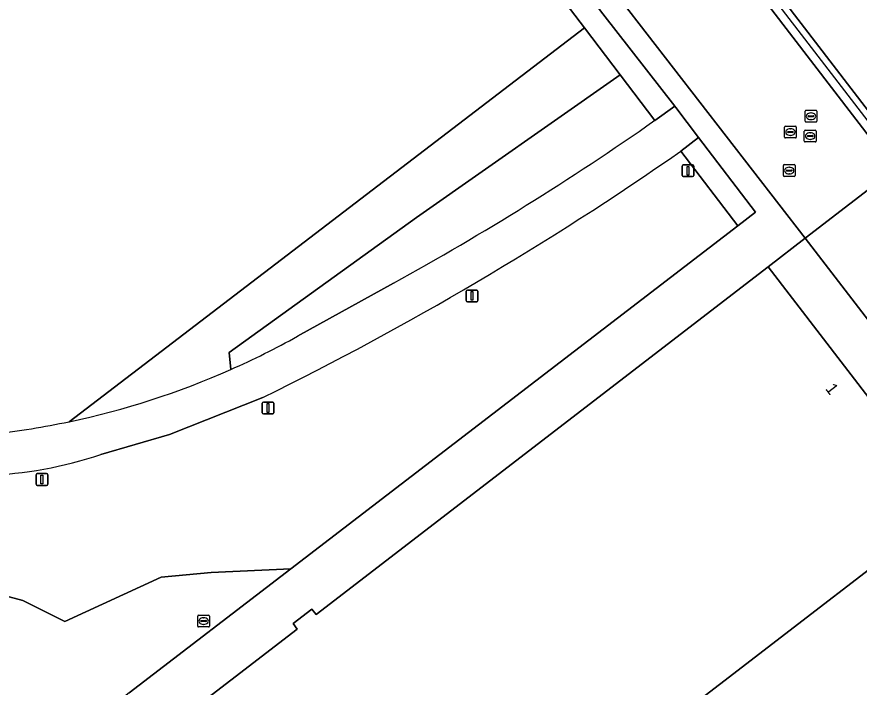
# Model space of a CAD drawing. Extents: x 155209 to 156748, y 385356 to 388487.
# Drawn here: x 156106.4 to 156177.8, y 385937.7 to 385994.6 of the extents above; entities that cross this region are included whole.
import ezdxf

# ---------------------------------------------------------------- set-up
doc = ezdxf.new("R2010")
doc.units = 0
for name, color, linetype in [('IMGEO_Grasland_agrarisch', 7, 'Continuous'), ('IMGEO_Groenvoorziening', 7, 'Continuous'), ('IMGEO_Haag', 7, 'Continuous'), ('IMGEO_Lichtmast', 7, 'Continuous'), ('IMGEO_Loofbos', 7, 'Continuous'), ('IMGEO_Pand', 7, 'Continuous'), ('IMGEO_Pand_nummerreeks', 7, 'Continuous'), ('IMGEO_Rijbaan_lokaal_gesloten', 7, 'Continuous'), ('IMGEO_Rijbaan_lokaal_open', 7, 'Continuous'), ('IMGEO_Rioolput', 7, 'Continuous'), ('IMGEO_Voetpad_gesloten', 7, 'Continuous'), ('IMGEO_Voetpad_open', 7, 'Continuous')]:
    doc.layers.add(name, color=color, linetype=linetype)

msp = doc.modelspace()

# ---------------------------------------------------------------- linework, layer by layer
at = {"layer": 'IMGEO_Grasland_agrarisch'}
msp.add_lwpolyline([(156220.549, 385968.739), (156185.49, 386016.084), (156167.209, 386001.475), (156278.587, 385856.453)], dxfattribs=at)
at = {"layer": 'IMGEO_Groenvoorziening'}
for points in [[(156285.514, 385849.881), (156284.854, 385850.065), (156278.587, 385856.453), (156167.209, 386001.475), (156185.49, 386016.084), (156184.674, 386017.186), (156177.537, 386011.492), (156166.201, 386002.568), (156165.304, 386001.86), (156168.669, 385997.526), (156180.839, 385981.624), (156184.09, 385977.376), (156195.93, 385961.982), (156207.756, 385946.593), (156219.573, 385931.238), (156231.41, 385915.868), (156241.752, 385902.4), (156255.401, 385884.633), (156266.626, 385870.03), (156277.503, 385855.777), (156277.531, 385855.74)], [(156157.568, 385989.652), (156154.535, 385993.632), (156110.792, 385960.218)], [(156124.515, 385964.645), (156124.385, 385966.102), (156140.278, 385977.551), (156157.568, 385989.652)], [(156160.509, 385985.793), (156157.568, 385989.652), (156140.278, 385977.551), (156124.385, 385966.102), (156124.515, 385964.645)], [(156167.554, 385976.836), (156162.729, 385983.183)], [(156088.771, 385944.146), (156096.563, 385945.599), (156102.938, 385946.083), (156106.886, 385945.056), (156110.425, 385943.255), (156118.61, 385947.023), (156122.858, 385947.408), (156129.607, 385947.725), (156167.554, 385976.836)], [(156130.189, 385967.476), (156138.317, 385971.979)], [(156127.24, 385962.271), (156119.321, 385959.145), (156113.496, 385957.432)], [(156129.607, 385947.725), (156122.858, 385947.408), (156118.61, 385947.023), (156110.425, 385943.255), (156106.886, 385945.056), (156102.938, 385946.083), (156096.563, 385945.599), (156088.771, 385944.146)], [(156115.909, 385937.216), (156129.607, 385947.725)]]:
    msp.add_lwpolyline(points, dxfattribs=at)
for centre, radius, start, end in [((156023.199, 386181.648), 239.193, 298.76895, 305.03364), ((156006.38, 386207.947), 273.795, 296.19475, 304.82294), ((156096.586, 386027.723), 68.985, 293.88235, 299.15078), ((156096.616, 386027.646), 68.902, 281.87329, 293.88581), ((156102.561, 385990.002), 34.357, 271.89192, 288.55928)]:
    msp.add_arc(centre, radius, start, end, dxfattribs=at)
at = {"layer": 'IMGEO_Haag'}
msp.add_lwpolyline([(156167.209, 386001.475), (156166.781, 386001.086), (156222.38, 385928.805), (156278.346, 385855.875), (156284.439, 385849.436), (156284.854, 385850.065), (156278.587, 385856.453)], close=True, dxfattribs=at)
at = {"layer": 'IMGEO_Lichtmast'}
for p, q in [((156162.821, 385981.114), (156162.821, 385981.914)), ((156162.821, 385981.914), (156162.821, 385981.114)), ((156162.921, 385982.014), (156163.711, 385982.014)), ((156163.711, 385982.014), (156162.921, 385982.014)), ((156163.811, 385981.914), (156163.811, 385981.114)), ((156163.811, 385981.114), (156163.811, 385981.914)), ((156163.711, 385981.014), (156162.921, 385981.014)), ((156162.921, 385981.014), (156163.711, 385981.014)), ((156144.507, 385970.494), (156144.507, 385971.294)), ((156144.507, 385971.294), (156144.507, 385970.494)), ((156144.607, 385971.394), (156145.397, 385971.394)), ((156145.397, 385971.394), (156144.607, 385971.394)), ((156145.497, 385971.294), (156145.497, 385970.494)), ((156145.497, 385970.494), (156145.497, 385971.294)), ((156145.397, 385970.394), (156144.607, 385970.394)), ((156144.607, 385970.394), (156145.397, 385970.394)), ((156127.193, 385960.984), (156127.193, 385961.784)), ((156127.193, 385961.784), (156127.193, 385960.984)), ((156127.293, 385961.884), (156128.083, 385961.884)), ((156128.083, 385961.884), (156127.293, 385961.884)), ((156128.183, 385961.784), (156128.183, 385960.984)), ((156128.183, 385960.984), (156128.183, 385961.784)), ((156128.083, 385960.884), (156127.293, 385960.884)), ((156127.293, 385960.884), (156128.083, 385960.884)), ((156107.995, 385954.916), (156107.995, 385955.716)), ((156107.995, 385955.716), (156107.995, 385954.916)), ((156108.095, 385955.816), (156108.885, 385955.816)), ((156108.885, 385955.816), (156108.095, 385955.816)), ((156108.985, 385955.716), (156108.985, 385954.916)), ((156108.985, 385954.916), (156108.985, 385955.716)), ((156108.885, 385954.816), (156108.095, 385954.816)), ((156108.095, 385954.816), (156108.885, 385954.816))]:
    msp.add_line(p, q, dxfattribs=at)
for points in [[(156163.241, 385981.889), (156163.391, 385981.889), (156163.391, 385981.139), (156163.241, 385981.139), (156163.241, 385981.889)], [(156144.927, 385971.269), (156145.077, 385971.269), (156145.077, 385970.519), (156144.927, 385970.519), (156144.927, 385971.269)], [(156127.613, 385961.759), (156127.763, 385961.759), (156127.763, 385961.009), (156127.613, 385961.009), (156127.613, 385961.759)], [(156108.415, 385955.691), (156108.565, 385955.691), (156108.565, 385954.941), (156108.415, 385954.941), (156108.415, 385955.691)]]:
    msp.add_lwpolyline(points, dxfattribs=at)
for centre, start, end in [((156162.921, 385981.914), 90, 180), ((156162.921, 385981.914), 90, 180), ((156163.711, 385981.914), 0, 90), ((156163.711, 385981.914), 360, 90), ((156162.921, 385981.114), 180, 270), ((156162.921, 385981.114), 180, 270), ((156163.711, 385981.114), 270, 0), ((156163.711, 385981.114), 270, 0), ((156144.607, 385971.294), 90, 180), ((156144.607, 385971.294), 90, 180), ((156145.397, 385971.294), 0, 90), ((156145.397, 385971.294), 360, 90), ((156144.607, 385970.494), 180, 270), ((156144.607, 385970.494), 180, 270), ((156145.397, 385970.494), 270, 0), ((156145.397, 385970.494), 270, 0), ((156127.293, 385961.784), 90, 180), ((156127.293, 385961.784), 90, 180), ((156128.083, 385961.784), 0, 90), ((156128.083, 385961.784), 360, 90), ((156127.293, 385960.984), 180, 270), ((156127.293, 385960.984), 180, 270), ((156128.083, 385960.984), 270, 0), ((156128.083, 385960.984), 270, 0), ((156108.095, 385955.716), 90, 180), ((156108.095, 385955.716), 90, 180), ((156108.885, 385955.716), 0, 90), ((156108.885, 385955.716), 360, 90), ((156108.095, 385954.916), 180, 270), ((156108.095, 385954.916), 180, 270), ((156108.885, 385954.916), 270, 0), ((156108.885, 385954.916), 270, 0)]:
    msp.add_arc(centre, 0.1, start, end, dxfattribs=at)
at = {"layer": 'IMGEO_Loofbos'}
msp.add_lwpolyline([(156110.792, 385960.218), (156154.535, 385993.632), (156144.769, 386006.447), (156173.258, 386028.793)], dxfattribs=at)
msp.add_arc((156096.443, 386028.664), 69.934, 276.51645, 281.83971, dxfattribs=at)
at = {"layer": 'IMGEO_Pand'}
msp.add_lwpolyline([(156146.274, 385922.751), (156185.717, 385953.089), (156170.127, 385973.357), (156131.765, 385943.857), (156131.406, 385944.305), (156129.815, 385943.105), (156130.161, 385942.624), (156050.588, 385881.441)], dxfattribs=at)
at = {"layer": 'IMGEO_Rijbaan_lokaal_gesloten'}
for points in [[(156277.531, 385855.74), (156277.503, 385855.777), (156266.626, 385870.03), (156255.401, 385884.633), (156241.752, 385902.4), (156231.41, 385915.868), (156219.573, 385931.238), (156207.756, 385946.593), (156195.93, 385961.982), (156184.09, 385977.376), (156180.839, 385981.624), (156173.28, 385975.806), (156273.756, 385845.152), (156253.997, 385829.921), (156263.096, 385818.018), (156247.187, 385805.769), (156251.992, 385799.487), (156244.172, 385793.446), (156247.412, 385789.224), (156247.701, 385788.833), (156251.441, 385783.91), (156235.908, 385771.977), (156239.22, 385767.734), (156228.894, 385759.732)], [(156273.756, 385845.152), (156173.28, 385975.806), (156170.127, 385973.357), (156185.717, 385953.089), (156146.274, 385922.751), (156150.528, 385917.222), (156156.102, 385921.509), (156164.09, 385911.123), (156158.516, 385906.837), (156160.857, 385903.793), (156200.3, 385934.128), (156216.362, 385913.247), (156216.482, 385913.09), (156177.035, 385882.729), (156191.619, 385863.794), (156231.059, 385894.15)]]:
    msp.add_lwpolyline(points, dxfattribs=at)
at = {"layer": 'IMGEO_Rijbaan_lokaal_open'}
msp.add_lwpolyline([(156165.304, 386001.86), (156166.201, 386002.568), (156177.537, 386011.492), (156184.674, 386017.186), (156187.011, 386019.05), (156185.798, 386019.909), (156176.524, 386026.479), (156150.284, 386005.616), (156156.897, 385996.959), (156157.631, 385995.998), (156173.28, 385975.806), (156180.839, 385981.624), (156168.669, 385997.526)], close=True, dxfattribs=at)
at = {"layer": 'IMGEO_Rioolput'}
for p, q in [((156173.261, 385985.717), (156173.261, 385986.569)), ((156173.336, 385986.643), (156174.188, 385986.643)), ((156173.52, 385986.137), (156173.52, 385986.149)), ((156173.958, 385986.1), (156173.56, 385986.1)), ((156173.563, 385986.186), (156173.961, 385986.186)), ((156173.749, 385986.423), (156173.774, 385986.423)), ((156174.004, 385986.149), (156174.004, 385986.137)), ((156174.262, 385986.569), (156174.262, 385985.717)), ((156171.59, 385985.296), (156172.442, 385985.296)), ((156174.188, 385985.643), (156173.336, 385985.643)), ((156173.772, 385985.863), (156173.747, 385985.863)), ((156171.515, 385984.37), (156171.515, 385985.222)), ((156171.774, 385984.79), (156171.774, 385984.802)), ((156172.212, 385984.753), (156171.814, 385984.753)), ((156171.817, 385984.839), (156172.215, 385984.839)), ((156172.003, 385985.076), (156172.028, 385985.076)), ((156172.258, 385984.802), (156172.258, 385984.79)), ((156172.516, 385985.222), (156172.516, 385984.37)), ((156173.196, 385984.031), (156173.196, 385984.883)), ((156173.271, 385984.957), (156174.123, 385984.957)), ((156173.684, 385984.737), (156173.709, 385984.737)), ((156174.197, 385984.883), (156174.197, 385984.031)), ((156172.442, 385984.296), (156171.59, 385984.296)), ((156172.026, 385984.516), (156172.001, 385984.516)), ((156174.123, 385983.957), (156173.271, 385983.957)), ((156173.455, 385984.451), (156173.455, 385984.463)), ((156173.893, 385984.414), (156173.495, 385984.414)), ((156173.498, 385984.5), (156173.896, 385984.5)), ((156173.707, 385984.177), (156173.682, 385984.177)), ((156173.939, 385984.463), (156173.939, 385984.451)), ((156171.416, 385981.107), (156171.416, 385981.959)), ((156171.491, 385982.033), (156172.343, 385982.033)), ((156171.904, 385981.813), (156171.929, 385981.813)), ((156172.417, 385981.959), (156172.417, 385981.107)), ((156172.343, 385981.033), (156171.491, 385981.033)), ((156171.675, 385981.527), (156171.675, 385981.539)), ((156172.113, 385981.49), (156171.715, 385981.49)), ((156171.718, 385981.576), (156172.116, 385981.576)), ((156171.927, 385981.253), (156171.902, 385981.253)), ((156172.159, 385981.539), (156172.159, 385981.527)), ((156121.716, 385942.873), (156121.716, 385943.725)), ((156121.791, 385943.799), (156122.643, 385943.799)), ((156121.975, 385943.293), (156121.975, 385943.305)), ((156122.413, 385943.256), (156122.015, 385943.256)), ((156122.018, 385943.342), (156122.416, 385943.342)), ((156122.204, 385943.579), (156122.229, 385943.579)), ((156122.459, 385943.305), (156122.459, 385943.293)), ((156122.717, 385943.725), (156122.717, 385942.873)), ((156122.643, 385942.799), (156121.791, 385942.799)), ((156122.227, 385943.019), (156122.202, 385943.019))]:
    msp.add_line(p, q, dxfattribs=at)
for points in [[(156173.261, 385985.717), (156173.261, 385986.569)], [(156173.336, 385986.643), (156174.188, 385986.643)], [(156174.262, 385986.569), (156174.262, 385985.717)], [(156171.59, 385985.296), (156172.442, 385985.296)], [(156174.188, 385985.643), (156173.336, 385985.643)], [(156171.515, 385984.37), (156171.515, 385985.222)], [(156172.516, 385985.222), (156172.516, 385984.37)], [(156173.196, 385984.031), (156173.196, 385984.883)], [(156173.271, 385984.957), (156174.123, 385984.957)], [(156174.197, 385984.883), (156174.197, 385984.031)], [(156172.442, 385984.296), (156171.59, 385984.296)], [(156174.123, 385983.957), (156173.271, 385983.957)], [(156171.416, 385981.107), (156171.416, 385981.959)], [(156171.491, 385982.033), (156172.343, 385982.033)], [(156172.417, 385981.959), (156172.417, 385981.107)], [(156172.343, 385981.033), (156171.491, 385981.033)], [(156121.716, 385942.873), (156121.716, 385943.725)], [(156121.791, 385943.799), (156122.643, 385943.799)], [(156122.717, 385943.725), (156122.717, 385942.873)], [(156122.643, 385942.799), (156121.791, 385942.799)]]:
    msp.add_lwpolyline(points, dxfattribs=at)
for centre, radius, start, end in [((156173.338, 385986.567), 0.0765, 91.55205, 178.44795), ((156173.338, 385986.567), 0.0765, 91.55205, 178.44795), ((156173.56, 385986.146), 0.0403, 85.87752, 175.75265), ((156173.557, 385986.136), 0.0366, 178.93798, 274.71019), ((156173.961, 385986.143), 0.043, 264.86636, 352.45326), ((156173.965, 385986.148), 0.0386, 1.73085, 96.63898), ((156174.186, 385986.567), 0.0765, 1.55205, 88.44795), ((156174.186, 385986.567), 0.0765, 1.55205, 88.44795), ((156171.592, 385985.22), 0.0765, 91.55205, 178.44795), ((156171.592, 385985.22), 0.0765, 91.55205, 178.44795), ((156172.44, 385985.22), 0.0765, 1.55205, 88.44795), ((156172.44, 385985.22), 0.0765, 1.55205, 88.44795), ((156173.338, 385985.719), 0.0765, 181.55205, 268.44795), ((156173.338, 385985.719), 0.0765, 181.55205, 268.44795), ((156174.186, 385985.719), 0.0765, 271.55205, 358.44795), ((156174.186, 385985.719), 0.0765, 271.55205, 358.44795), ((156171.814, 385984.799), 0.0403, 85.87752, 175.75265), ((156171.811, 385984.789), 0.0366, 178.93798, 274.71019), ((156172.215, 385984.796), 0.043, 264.86636, 352.45326), ((156172.219, 385984.801), 0.0386, 1.73085, 96.63898), ((156173.273, 385984.881), 0.0765, 91.55205, 178.44795), ((156173.273, 385984.881), 0.0765, 91.55205, 178.44795), ((156174.121, 385984.881), 0.0765, 1.55205, 88.44795), ((156174.121, 385984.881), 0.0765, 1.55205, 88.44795), ((156171.592, 385984.372), 0.0765, 181.55205, 268.44795), ((156171.592, 385984.372), 0.0765, 181.55205, 268.44795), ((156172.44, 385984.372), 0.0765, 271.55205, 358.44795), ((156172.44, 385984.372), 0.0765, 271.55205, 358.44795), ((156173.273, 385984.033), 0.0765, 181.55205, 268.44795), ((156173.273, 385984.033), 0.0765, 181.55205, 268.44795), ((156173.495, 385984.46), 0.0403, 85.87752, 175.75265), ((156173.492, 385984.45), 0.0366, 178.93798, 274.71019), ((156173.896, 385984.457), 0.043, 264.86636, 352.45326), ((156173.9, 385984.462), 0.0386, 1.73085, 96.63898), ((156174.121, 385984.033), 0.0765, 271.55205, 358.44795), ((156174.121, 385984.033), 0.0765, 271.55205, 358.44795), ((156171.493, 385981.957), 0.0765, 91.55205, 178.44795), ((156171.493, 385981.957), 0.0765, 91.55205, 178.44795), ((156172.341, 385981.957), 0.0765, 1.55205, 88.44795), ((156172.341, 385981.957), 0.0765, 1.55205, 88.44795), ((156171.493, 385981.109), 0.0765, 181.55205, 268.44795), ((156171.493, 385981.109), 0.0765, 181.55205, 268.44795), ((156171.715, 385981.536), 0.0403, 85.87752, 175.75265), ((156171.712, 385981.526), 0.0366, 178.93798, 274.71019), ((156172.116, 385981.533), 0.043, 264.86636, 352.45326), ((156172.12, 385981.538), 0.0386, 1.73085, 96.63898), ((156172.341, 385981.109), 0.0765, 271.55205, 358.44795), ((156172.341, 385981.109), 0.0765, 271.55205, 358.44795), ((156121.793, 385943.723), 0.0765, 91.55205, 178.44795), ((156121.793, 385943.723), 0.0765, 91.55205, 178.44795), ((156122.015, 385943.302), 0.0403, 85.87752, 175.75265), ((156122.012, 385943.292), 0.0366, 178.93798, 274.71019), ((156122.416, 385943.299), 0.043, 264.86636, 352.45326), ((156122.42, 385943.304), 0.0386, 1.73085, 96.63898), ((156122.641, 385943.723), 0.0765, 1.55205, 88.44795), ((156122.641, 385943.723), 0.0765, 1.55205, 88.44795), ((156121.793, 385942.875), 0.0765, 181.55205, 268.44795), ((156121.793, 385942.875), 0.0765, 181.55205, 268.44795), ((156122.641, 385942.875), 0.0765, 271.55205, 358.44795), ((156122.641, 385942.875), 0.0765, 271.55205, 358.44795)]:
    msp.add_arc(centre, radius, start, end, dxfattribs=at)
for centre, major_axis, ratio, start_param, end_param in [((156173.748, 385986.143), (-0.387, 0.002), 0.722429, 4.712389, 7.853982), ((156173.773, 385986.143), (-0.39, 0.002), 0.717154, 1.570796, 4.712389), ((156172.002, 385984.796), (-0.387, 0.002), 0.722429, 4.712389, 7.853982), ((156172.027, 385984.796), (-0.39, 0.002), 0.717154, 1.570796, 4.712389), ((156173.683, 385984.457), (-0.387, 0.002), 0.722429, 4.712389, 7.853982), ((156173.708, 385984.457), (-0.39, 0.002), 0.717154, 1.570796, 4.712389), ((156171.903, 385981.533), (-0.387, 0.002), 0.722429, 4.712389, 7.853982), ((156171.928, 385981.533), (-0.39, 0.002), 0.717154, 1.570796, 4.712389), ((156122.203, 385943.299), (-0.387, 0.002), 0.722429, 4.712389, 7.853982), ((156122.228, 385943.299), (-0.39, 0.002), 0.717154, 1.570796, 4.712389)]:
    msp.add_ellipse(centre, major_axis=major_axis, ratio=ratio, start_param=start_param, end_param=end_param, dxfattribs=at)
at = {"layer": 'IMGEO_Voetpad_gesloten'}
for points in [[(156162.729, 385983.183), (156164.223, 385984.332), (156162.28, 385986.884), (156162.197, 385986.99), (156160.509, 385985.793)], [(156138.317, 385971.979), (156130.189, 385967.476)], [(156113.496, 385957.432), (156119.321, 385959.145), (156127.24, 385962.271)]]:
    msp.add_lwpolyline(points, dxfattribs=at)
for centre, radius, start, end in [((156023.199, 386181.648), 239.193, 298.76895, 305.03364), ((156006.38, 386207.947), 273.795, 296.19475, 304.82294), ((156096.586, 386027.723), 68.985, 293.88235, 299.15078), ((156096.616, 386027.646), 68.902, 281.87329, 293.88581), ((156096.443, 386028.664), 69.934, 276.51645, 281.83971), ((156102.561, 385990.002), 34.357, 271.89192, 288.55928)]:
    msp.add_arc(centre, radius, start, end, dxfattribs=at)
at = {"layer": 'IMGEO_Voetpad_open'}
for points in [[(156174.878, 386027.645), (156173.258, 386028.793), (156144.769, 386006.447), (156154.535, 385993.632), (156157.568, 385989.652), (156160.509, 385985.793), (156162.197, 385986.99), (156156.096, 385994.825), (156155.384, 385995.757), (156147.591, 386005.96)], [(156164.223, 385984.332), (156162.729, 385983.183), (156167.554, 385976.836), (156169.049, 385978.012)]]:
    msp.add_lwpolyline(points, close=True, dxfattribs=at)
for points in [[(156130.161, 385942.624), (156129.815, 385943.105), (156131.406, 385944.305), (156131.765, 385943.857), (156170.127, 385973.357), (156173.28, 385975.806), (156157.631, 385995.998), (156156.897, 385996.959), (156150.284, 386005.616), (156176.524, 386026.479), (156174.878, 386027.645), (156147.591, 386005.96), (156155.384, 385995.757), (156156.096, 385994.825), (156162.197, 385986.99), (156162.28, 385986.884), (156164.223, 385984.332), (156169.049, 385978.012), (156167.554, 385976.836), (156129.607, 385947.725), (156115.909, 385937.216), (156108.348, 385931.389), (156077.969, 385907.974), (156069.761, 385901.652)], [(156050.588, 385881.441), (156130.161, 385942.624)]]:
    msp.add_lwpolyline(points, dxfattribs=at)

# ---------------------------------------------------------------- texts
at = {"layer": 'IMGEO_Pand_nummerreeks'}
msp.add_text('1', height=1, rotation=307.56863, dxfattribs=at).set_placement((156174.935, 385963.004))

doc.saveas('drawing.dxf')
